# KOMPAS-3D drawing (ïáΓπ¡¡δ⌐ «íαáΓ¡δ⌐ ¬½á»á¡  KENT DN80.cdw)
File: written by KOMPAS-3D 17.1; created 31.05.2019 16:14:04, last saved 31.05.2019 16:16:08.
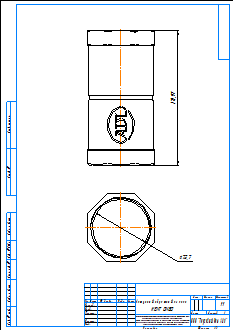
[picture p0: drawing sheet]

Sheet 1: A3, portrait

Title block, sheet 1: name: Латунный обратный клапан / KENT DN80; material: Внимание! Данный продукт является объектом авторского права ООО «Торговый Дом АДЛ». / Запрещается изменение, копирование, распространение / (в том числе путем копирования на другие сайты и ресурсы в Интернете) / или любое иное использование информации и объектов без предварительного / согласия правообладателя (ООО «Торговый Дом АДЛ»).; sheets: 1; organisation: ООО "Торговый дом АДЛ"; sheet format: A3

Views: Вид 1, Проекционный вид 2
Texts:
  user
Dimensions and other numbers on the sheet: 72,7; 171,97; 1:1; 1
